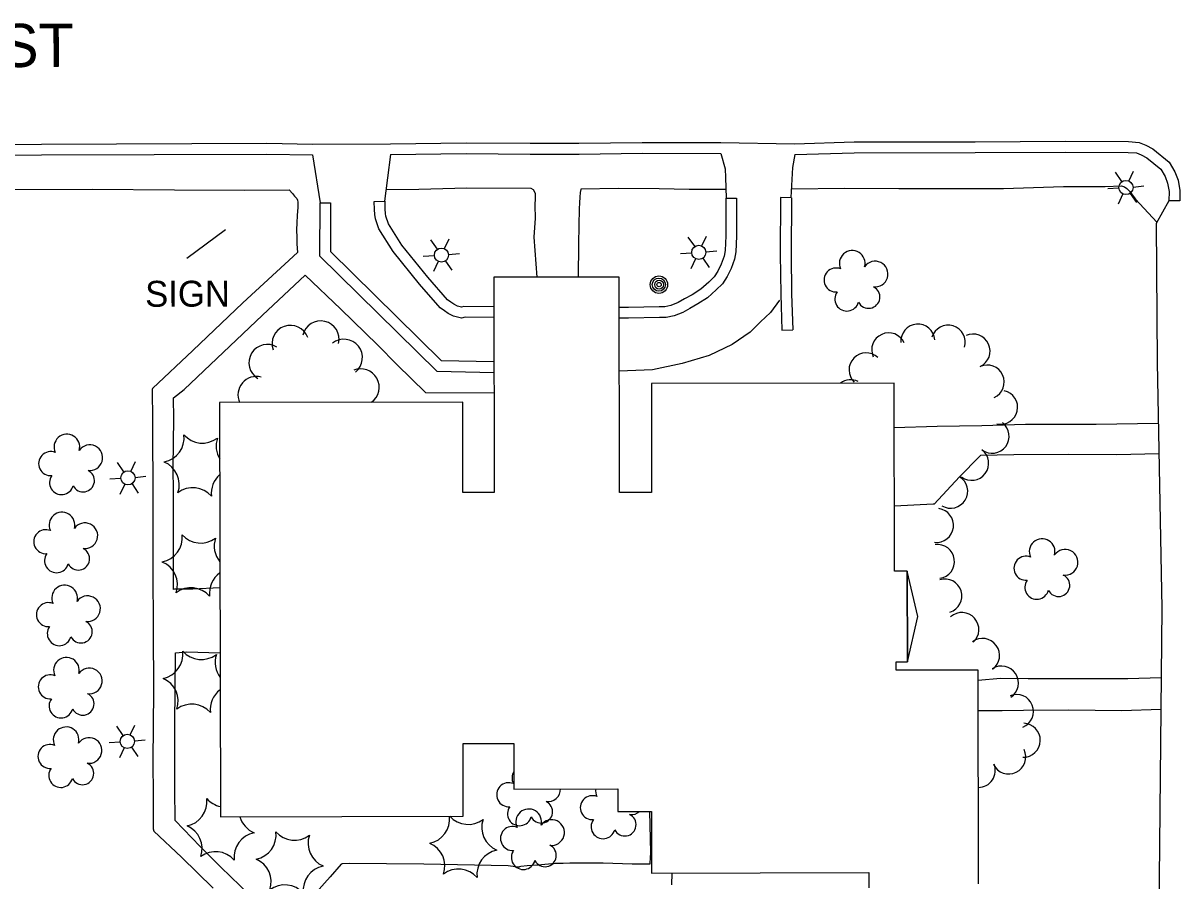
# Model space of a CAD drawing. Extents: x 189384 to 193282, y 256970 to 260388.
# Drawn here: x 190826 to 191093.6, y 257790.7 to 257989.2 of the extents above; entities that cross this region are included whole.
import ezdxf

# ---------------------------------------------------------------- set-up
doc = ezdxf.new("R2010")
doc.units = 0
for name, color, linetype in [('E_DWY', 7, 'Continuous'), ('E_LAND_Vegetation', 7, 'Continuous'), ('E_MISCPROP', 7, 'Continuous'), ('E_MISCPROP_HvyLine', 7, 'Continuous'), ('E_PATH_Sidewalk', 7, 'Continuous'), ('E_RDWY', 7, 'Continuous'), ('E_RDWY_Name', 7, 'Continuous')]:
    doc.layers.add(name, color=color, linetype=linetype)

# ---------------------------------------------------------------- blocks, each defined once
blk = doc.blocks.new('LTP_8')
at = {"layer": 'E_MISCPROP'}
for p, q in [((-0.8, 1.43), (-2, 3.73)), ((0.9, 1.42), (2.27, 3.65)), ((-1.64, 0.07), (-4.24, 0.14)), ((-0.88, -1.42), (-2.24, -3.61)), ((0.76, -1.47), (2, -3.65)), ((1.64, -0.02), (4.16, -0.09))]:
    blk.add_line(p, q, dxfattribs=at)
blk.add_circle((0, 0), 1.64, dxfattribs=at)
blk = doc.blocks.new('POLE_7')
at = {"layer": 'E_MISCPROP'}
for centre, radius in [((-0.01, 0.02), 2.02), ((-0.01, 0.03), 1.52), ((0, -0.01), 1.01), ((0, 0), 0.502)]:
    blk.add_circle(centre, radius, dxfattribs=at)
blk = doc.blocks.new('LTP_10')
at = {"layer": 'E_MISCPROP'}
for p, q in [((-0.8, 1.43), (-2, 3.73)), ((0.9, 1.42), (2.27, 3.65)), ((-1.64, 0.07), (-4.24, 0.14)), ((-0.88, -1.42), (-2.24, -3.61)), ((0.76, -1.47), (2, -3.65)), ((1.64, -0.02), (4.16, -0.09))]:
    blk.add_line(p, q, dxfattribs=at)
blk.add_circle((0, 0), 1.64, dxfattribs=at)
blk = doc.blocks.new('SIGN_6')
at = {"layer": 'E_MISCPROP'}
blk.add_text('SIGN', height=6, rotation=0, dxfattribs=at).set_placement((0, -3))
blk = doc.blocks.new('TREE_5')
at = {"layer": 'E_LAND_Vegetation'}
for centre, radius, start, end in [((-1.47, 4.28), 2.78, 1.3945, 209.1675), ((3.57, 2.42), 2.97, 278.4236, 139.6575), ((-4.47, 0.2), 2.78, 78.0716, 279.0826), ((-2.01, -4.2), 2.61, 140.7797, 358.7123), ((3.46, -3.43), 2.97, 196.0745, 79.0477)]:
    blk.add_arc(centre, radius, start, end, dxfattribs=at)
blk = doc.blocks.new('PINEL_1')
at = {"layer": 'E_LAND_Vegetation'}
for centre, start, end in [((-8.14, 7.32), 275.2112, 0.9762), ((2.26, 10.71), 215.2112, 300.9762), ((10.41, 3.41), 155.2113, 240.9762), ((-10.4, -3.39), 335.2112, 60.9762), ((8.15, -7.3), 95.2113, 180.9762), ((-2.25, -10.7), 35.2113, 120.9762)]:
    blk.add_arc(centre, 5.72, start, end, dxfattribs=at)
blk = doc.blocks.new('TREE_6')
at = {"layer": 'E_LAND_Vegetation'}
for centre, radius, start, end in [((-1.47, 4.28), 2.78, 1.3947, 209.1677), ((3.57, 2.42), 2.97, 278.4238, 139.6577), ((-4.47, 0.2), 2.78, 78.0717, 279.0828), ((-2.01, -4.2), 2.61, 140.7799, 358.7125), ((3.46, -3.43), 2.97, 196.0746, 79.0479)]:
    blk.add_arc(centre, radius, start, end, dxfattribs=at)

msp = doc.modelspace()

# ---------------------------------------------------------------- linework, layer by layer
at = {"layer": 'E_DWY'}
for points in [[(190892.93, 257958.69), (190894.7, 257947.6)], [(190911, 257958.77), (190909.63, 257947.96)], [(190987.43, 257959.05), (190988.39, 257955.47), (190988.46, 257953.46), (190988.64, 257948.67)], [(191004.55, 257958.8), (191003.97, 257955.82), (191003.63, 257948.81)], [(190894.6, 257947.6), (190894.59, 257935.32), (190921.68, 257908.64), (190934.94, 257908.37)], [(190894.6, 257947.6), (190897.1, 257947.59), (190897.09, 257936.36), (190922.73, 257911.12), (190934.93, 257910.88)], [(190934.91, 257921.08), (190928.25, 257921.12), (190927.38, 257920.89), (190925.57, 257921.38), (190924.32, 257922.02), (190923.47, 257922.63), (190922.51, 257923.33), (190917.73, 257928.78), (190911.58, 257936.34), (190908.25, 257941.63), (190907.48, 257943.89), (190907.33, 257944.89), (190907.26, 257946.05), (190907.23, 257947.92), (190909.73, 257947.96)], [(190934.91, 257923.58), (190927.95, 257923.62), (190927.4, 257923.48), (190926.48, 257923.72), (190925.64, 257924.16), (190924.93, 257924.66), (190924.2, 257925.19), (190919.64, 257930.39), (190913.61, 257937.8), (190910.52, 257942.72), (190909.92, 257944.49), (190909.81, 257945.16), (190909.76, 257946.14), (190909.73, 257947.96)], [(190988.54, 257948.67), (190991.04, 257948.68), (190991.07, 257939.91), (190990.91, 257936.28), (190990.59, 257934.61), (190989.78, 257932.45), (190988.87, 257930.6), (190987.8, 257928.89), (190986.36, 257927.45), (190984.34, 257925.65), (190982.1, 257924.21), (190980.24, 257923.17), (190978.58, 257922.27), (190976.59, 257921.45), (190974.73, 257921.09), (190973.21, 257921.04), (190966.06, 257920.9), (190963.87, 257920.91)], [(190988.54, 257948.67), (190988.57, 257939.96), (190988.42, 257936.57), (190988.17, 257935.29), (190987.48, 257933.45), (190986.69, 257931.82), (190985.83, 257930.46), (190984.64, 257929.27), (190982.82, 257927.64), (190980.81, 257926.35), (190979.04, 257925.37), (190977.51, 257924.54), (190975.86, 257923.86), (190974.45, 257923.58), (190973.15, 257923.54), (190966.04, 257923.4), (190963.87, 257923.41)], [(191003.73, 257948.8), (191001.23, 257948.82), (191001.15, 257935.73), (191001.27, 257926.51), (191001.54, 257918.17), (191004.04, 257918.25)], [(191003.73, 257948.8), (191003.65, 257935.74), (191003.77, 257926.57), (191004.04, 257918.25)], [(191001.01, 257925.07), (190998.93, 257922.26), (190996.56, 257920.07), (190994.2, 257917.69), (190990.01, 257914.82), (190984.74, 257912.32), (190978.49, 257910.46), (190971.59, 257908.97), (190963.89, 257908.69)]]:
    msp.add_lwpolyline(points, dxfattribs=at)
at = {"layer": 'E_LAND_Vegetation'}
for centre, radius, start, end in [((190894.84, 257916.03), 4.26, 346.7672, 166.7518), ((190887.83, 257915.01), 4.26, 19.7147, 199.6994), ((191026.24, 257913.59), 3.93, 24.185, 204.1697), ((191032.98, 257915.62), 3.93, 4.3542, 184.3388), ((191040.01, 257915.37), 3.93, 343.2245, 163.2092), ((190882.5, 257910.6), 4.26, 58.5568, 238.5415), ((190900.23, 257911.79), 4.26, 308.6434, 128.628), ((191045.77, 257913.31), 3.93, 294.5118, 114.4964), ((191021, 257908.97), 3.93, 45.9785, 225.9632), ((191049.03, 257906.15), 3.93, 294.5118, 114.4964), ((190879.96, 257903.18), 4.26, 75.0231, 204.5396), ((190904.11, 257904.94), 4.26, 305.4973, 112.6623), ((191017.43, 257902.74), 3.93, 63.5477, 126.9617), ((191052.14, 257900.29), 3.93, 257.4746, 77.4592), ((191050.18, 257893.61), 3.93, 232.9751, 52.9598), ((190857.51, 257893.25), 5.72, 281.2383, 7.0033), ((190867.49, 257897.72), 5.72, 221.2384, 307.0033), ((190876.36, 257891.31), 5.72, 161.2384, 211.182), ((191045.44, 257887.33), 3.93, 232.9751, 52.9598), ((190856.39, 257882.36), 5.72, 341.2383, 67.0033), ((190875.24, 257880.42), 5.72, 131.1894, 187.0033), ((191040.59, 257880.88), 3.93, 238.7716, 58.7563), ((190865.25, 257875.95), 5.72, 41.2383, 127.0033), ((191037.32, 257872.96), 3.93, 262.8301, 82.8148), ((190857.08, 257870.11), 5.72, 281.2383, 7.0033), ((190867.07, 257874.59), 5.72, 221.2384, 307.0033), ((190875.93, 257868.18), 5.72, 161.2384, 219.3716), ((191037.53, 257864.63), 3.93, 277.8452, 97.8299), ((190855.96, 257859.23), 5.72, 341.2383, 67.0033), ((190874.81, 257857.29), 5.72, 125.1993, 187.0033), ((191039.26, 257856.64), 3.93, 287.1398, 107.1245), ((190864.82, 257852.82), 5.72, 41.2383, 127.0033), ((191043.18, 257848.88), 3.93, 311.5325, 131.5172), ((191047.96, 257842.88), 3.93, 306.2697, 126.2544), ((190857.26, 257843.18), 5.72, 281.2383, 7.0033), ((190867.25, 257847.65), 5.72, 221.2384, 307.0033), ((190876.11, 257841.24), 5.72, 161.2384, 217.2891), ((191052.33, 257836.5), 3.93, 302.9103, 122.895), ((190856.14, 257832.29), 5.72, 341.2383, 67.0033), ((190874.99, 257830.35), 5.72, 126.7895, 187.0033), ((191055.82, 257829.92), 3.93, 292.1159, 112.1006), ((190865.01, 257825.88), 5.72, 41.2383, 127.0033), ((191057.38, 257823.24), 3.93, 268.4425, 88.4272), ((191054.04, 257819.37), 3.93, 205.7898, 25.7744), ((190942.08, 257814.5), 2.97, 148.7606, 205.6846), ((191046.98, 257816.27), 3.93, 270.0608, 21.7062), ((190938.33, 257810.64), 2.78, 67.4216, 275.1946), ((190947.38, 257812.02), 2.97, 262.1015, 359.3814), ((190957.67, 257807.65), 2.78, 67.4216, 275.1946), ((190961.41, 257811.5), 2.97, 170.3003, 205.6846), ((190862.8, 257809.05), 5.72, 281.2383, 7.0033), ((190872.79, 257813.52), 5.72, 221.2384, 258.2186), ((190940.84, 257806.24), 2.78, 144.0986, 345.1096), ((190945.86, 257806.71), 2.61, 206.8067, 64.7393), ((190881.65, 257807.11), 5.72, 195.7078, 247.0033), ((190918.96, 257805.02), 5.72, 281.2383, 6.3944), ((190928.95, 257809.49), 5.72, 222.0512, 307.0033), ((190965.19, 257803.71), 2.61, 206.8067, 64.7393), ((190966.72, 257809.02), 2.97, 262.1015, 311.5174), ((190861.68, 257798.17), 5.72, 341.2383, 67.0033), ((190937.82, 257803.08), 5.72, 161.2384, 247.0033), ((190960.17, 257803.25), 2.78, 144.0986, 345.1096), ((190880.53, 257796.23), 5.72, 101.2384, 187.0033), ((190870.54, 257791.75), 5.72, 41.2383, 127.0033), ((190917.84, 257794.13), 5.72, 341.2383, 67.0033), ((190936.69, 257792.19), 5.72, 101.2384, 187.0033), ((190926.71, 257787.72), 5.72, 41.2383, 127.0033)]:
    msp.add_arc(centre, radius, start, end, dxfattribs=at)
at = {"layer": 'E_MISCPROP'}
msp.add_line((190863.88, 257934.84), (190872.83, 257941.45), dxfattribs=at)
at = {"layer": 'E_MISCPROP_HvyLine'}
msp.add_lwpolyline([(191047.03, 257790.06), (191046.93, 257839.49), (191027.98, 257839.46), (191027.98, 257841.37), (191030.59, 257841.38), (191030.54, 257862.38), (191027.58, 257862.38), (191027.5, 257905.91), (190971.34, 257905.8), (190971.39, 257880.6), (190963.95, 257880.59), (190963.85, 257930.44), (190934.9, 257930.38), (190934.99, 257880.58), (190927.75, 257880.57), (190927.7, 257901.51), (190871.44, 257901.4), (190871.62, 257805.55), (190927.79, 257805.66), (190927.76, 257822.5), (190939.52, 257822.52), (190939.54, 257811.96), (190963.6, 257812.01), (190963.61, 257806.78), (190971.36, 257806.8), (190971.39, 257792.52), (191021.62, 257792.62), (191021.63, 257789.08)], dxfattribs=at)
msp.add_lwpolyline([(191030.59, 257841.38), (191032.99, 257851.89), (191030.54, 257862.38)], close=True, dxfattribs=at)
at = {"layer": 'E_PATH_Sidewalk'}
for points in [[(190821.37, 257950.7), (190841.98, 257950.77), (190861.01, 257950.6), (190877.11, 257950.56), (190887.51, 257950.59), (190888.29, 257949.78), (190888.79, 257949.19), (190889.28, 257948.62), (190889.47, 257948.25), (190889.53, 257947.73), (190889.53, 257946.63), (190889.37, 257944.66), (190889.28, 257942.95), (190889.25, 257941.35), (190889.32, 257939.62), (190889.35, 257938.12), (190889.44, 257936.12), (190876.85, 257924.44), (190865.28, 257913.42), (190855.96, 257904.68), (190855.83, 257904.45), (190855.96, 257897.29), (190856.03, 257878.29), (190856.02, 257862.85), (190856.05, 257848.83), (190856.13, 257834.66), (190855.99, 257818.46), (190856.06, 257810.33), (190856.04, 257802.73), (190856.2, 257802.19), (190862.64, 257796.23), (190869.93, 257789.03)], [(190909.98, 257950.69), (190917.55, 257950.74), (190928.66, 257951.11), (190943.46, 257951), (190943.99, 257950.7), (190944.43, 257949.88), (190944.42, 257948.76), (190944.36, 257946.97), (190944.46, 257944.05), (190944.16, 257939.67), (190944.84, 257930.4)], [(190954.49, 257930.42), (190954.56, 257938.04), (190954.64, 257942.36), (190954.73, 257946.2), (190954.77, 257947.61), (190954.88, 257948.89), (190954.97, 257949.97), (190955.07, 257950.68), (190955.09, 257950.82), (190963.67, 257951), (190973.17, 257950.93), (190980.1, 257950.81), (190988.56, 257950.78)], [(191003.73, 257950.83), (191016.04, 257951), (191028.58, 257950.96), (191042.81, 257950.95), (191052.82, 257950.95), (191066.72, 257951.37), (191076.34, 257951.36), (191080.08, 257951.52), (191080.77, 257951.29), (191081.36, 257950.95), (191082, 257950.23), (191082.58, 257949.47), (191083.37, 257948.47), (191088.28, 257943.14)], [(190871.52, 257858.5), (190865.25, 257858.21), (190861.04, 257858.18), (190860.8, 257858.17), (190860.81, 257871.22), (190860.79, 257880.64), (190860.68, 257886.36), (190860.85, 257897.67), (190860.78, 257902.48), (190863.24, 257904.45), (190881.37, 257921.59), (190891.25, 257930.91), (190899.48, 257922.97), (190907.94, 257914.72), (190912.55, 257910.13), (190919.07, 257903.7), (190934.95, 257903.65)], [(191088.62, 257896.52), (191074.24, 257896.3), (191057.91, 257896.29), (191047.82, 257895.97), (191037.44, 257895.89), (191027.52, 257895.54)], [(191088.75, 257889.55), (191079.01, 257889.32), (191067.84, 257889.35), (191055.22, 257889.32), (191047.52, 257889.11), (191047.27, 257888.9), (191042.64, 257884.23), (191036.79, 257877.9), (191036.53, 257877.85), (191027.55, 257877.42)], [(190878.46, 257787.42), (190871.7, 257793.89), (190866.98, 257798.63), (190861.16, 257804.66), (190861.08, 257811.93), (190861.11, 257826.87), (190861.24, 257843.46), (190863.77, 257843.7), (190871.55, 257843.49)], [(191089.27, 257837.7), (191081.59, 257837.47), (191070.55, 257837.46), (191058.55, 257837.48), (191052.11, 257837.56), (191046.94, 257837.08)], [(191089.2, 257830.39), (191080.17, 257830.07), (191067.86, 257830.2), (191057.44, 257830.17), (191052.5, 257830.05), (191046.95, 257830.09)], [(190970.92, 257806.79), (190971.1, 257797.31), (190970.98, 257794.77), (190970.95, 257794.6), (190966.9, 257794.57), (190960.21, 257794.8), (190954.93, 257794.81), (190952.5, 257794.82), (190950.94, 257794.76), (190949.09, 257794.73), (190945.17, 257794.34), (190942.58, 257794.22), (190941.16, 257794), (190940.86, 257793.94), (190940.72, 257793.91), (190940.46, 257793.88), (190938.2, 257794.16), (190918.72, 257794.59), (190901.44, 257794.72), (190899.77, 257794.65), (190899.59, 257794.61), (190897.06, 257791.66), (190889.97, 257783.72)], [(190976.07, 257789.79), (190976.18, 257792.53)]]:
    msp.add_lwpolyline(points, dxfattribs=at)
at = {"layer": 'E_RDWY'}
for points in [[(190695.6, 257957.83), (190695.52, 257960.33), (190711.56, 257960.83), (190745.08, 257960.99), (190790.56, 257961.05), (190830.23, 257961.22), (190882.37, 257961.39), (190892.97, 257961.19), (190910.97, 257961.27)], [(190910.97, 257961.27), (190928.46, 257961.51), (190943.33, 257961.39), (190954.58, 257961.4)], [(190954.58, 257961.4), (190969.23, 257961.59), (190987.43, 257961.55)], [(190987.43, 257961.55), (191004.48, 257961.3), (191018.24, 257961.7), (191046.26, 257961.75), (191067.1, 257961.86), (191081.75, 257961.79), (191084.17, 257961.61), (191085.75, 257960.98), (191087.38, 257960.11), (191091.13, 257957.05), (191092.45, 257954.79), (191093.18, 257952.82), (191093.61, 257950.47), (191093.58, 257948.05), (191091.08, 257948.08)], [(190695.6, 257957.83), (190711.61, 257958.33), (190745.09, 257958.49), (190790.57, 257958.55), (190830.24, 257958.72), (190882.36, 257958.89), (190892.93, 257958.69)], [(190911, 257958.77), (190928.46, 257959.01), (190943.31, 257958.89), (190954.61, 257958.9)], [(190954.61, 257958.9), (190969.24, 257959.09), (190987.43, 257959.05)], [(191004.55, 257958.8), (191018.28, 257959.2), (191046.27, 257959.25), (191067.11, 257959.36), (191081.65, 257959.29), (191083.6, 257959.15), (191084.69, 257958.71), (191085.99, 257958.01), (191089.2, 257955.39), (191090.19, 257953.71), (191090.76, 257952.16), (191091.1, 257950.25), (191091.08, 257948.08)], [(191091.08, 257948.08), (191088.11, 257942.84), (191088.36, 257910.69), (191089.42, 257853.83), (191088.85, 257791.34), (191088.79, 257745.02)]]:
    msp.add_lwpolyline(points, dxfattribs=at)

# ---------------------------------------------------------------- block references
at = {"layer": 'E_LAND_Vegetation'}
for name, p, xscale, yscale, rotation in [('TREE_5', (191018.57, 257929.36), 0.9999977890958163, 0.9999977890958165, 66.02718400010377), ('TREE_5', (191062.51, 257862.66), 0.9999977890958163, 0.9999977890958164, 66.02718321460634), ('TREE_5', (190943.72, 257800.13), 0.9999977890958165, 0.9999977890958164, 66.0271853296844), ('PINEL_1', (190887.66, 257794.94), 0.9999977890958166, 0.9999977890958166, 66.02718632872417)]:
    msp.add_blockref(name, p, dxfattribs=dict(at, xscale=xscale, yscale=yscale, rotation=rotation))
for p, rotation in [((190836.87, 257886.87), 66.02694352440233), ((190835.74, 257868.8), 66.02694354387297), ((190836.36, 257851.92), 66.0269435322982), ((190836.77, 257835.21), 66.02694352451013), ((190836.7, 257819.11), 66.02694352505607)]:
    msp.add_blockref('TREE_6', p, dxfattribs=dict(at, rotation=rotation))
at = {"layer": 'E_MISCPROP'}
for name, p, xscale, yscale, rotation in [('LTP_8', (191081.14, 257951.16), 1.0000015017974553, 1.0000015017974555, 66.23274123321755), ('LTP_10', (190922.77, 257935.52), 1.0000015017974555, 1.0000015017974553, 66.2327440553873), ('LTP_8', (190982.31, 257936.15), 1.0000015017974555, 1.000001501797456, 66.23274299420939), ('POLE_7', (190973.11, 257928.68), 1.0000015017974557, 1.0000015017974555, 66.23274315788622), ('SIGN_6', (190854.22, 257926.55), 0.999998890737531, 0.9999988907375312, 0.19332607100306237), ('LTP_10', (190850.24, 257883.97), 1.0000015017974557, 1.0000015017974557, 66.23274534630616), ('LTP_10', (190850.1, 257822.99), 1.0000015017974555, 1.0000015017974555, 66.23274534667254)]:
    msp.add_blockref(name, p, dxfattribs=dict(at, xscale=xscale, yscale=yscale, rotation=rotation))

# ---------------------------------------------------------------- texts
at = {"layer": 'E_RDWY_Name'}
msp.add_text('MARGARET ST', height=10, rotation=0.267, dxfattribs=at).set_placement((190741.17, 257978.65))

doc.saveas('drawing.dxf')
